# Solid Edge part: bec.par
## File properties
Author: user
Template: Iso Part.par
Last saved by: user
Revision: 2
Application: Solid Edge
Accuracy: 0.990
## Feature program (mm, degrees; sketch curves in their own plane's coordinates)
sketch for "unnamed RevolvedProtrusion 1" plane through (0, 0, 0) normal (0, -1, 0) x-axis (1, 0, 0)
  line (0, 100) -> (0, -100)
revolve "unnamed RevolvedProtrusion 1" add finite 360 deg
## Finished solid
Body 1: solid body, 1 face, 0 edges, 0 vertices.
  Faces by surface: sphere 1
Spherical faces by radius (mm): R100 x1
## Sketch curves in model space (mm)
arc centre (0, 0, 0) radius 100 from (0, 0, 100) through (99.9561, 0, -2.9633) to (0, 0, -100)
line (0, 0, 100) -> (0, 0, -100)
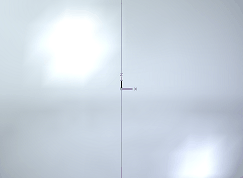
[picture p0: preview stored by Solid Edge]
